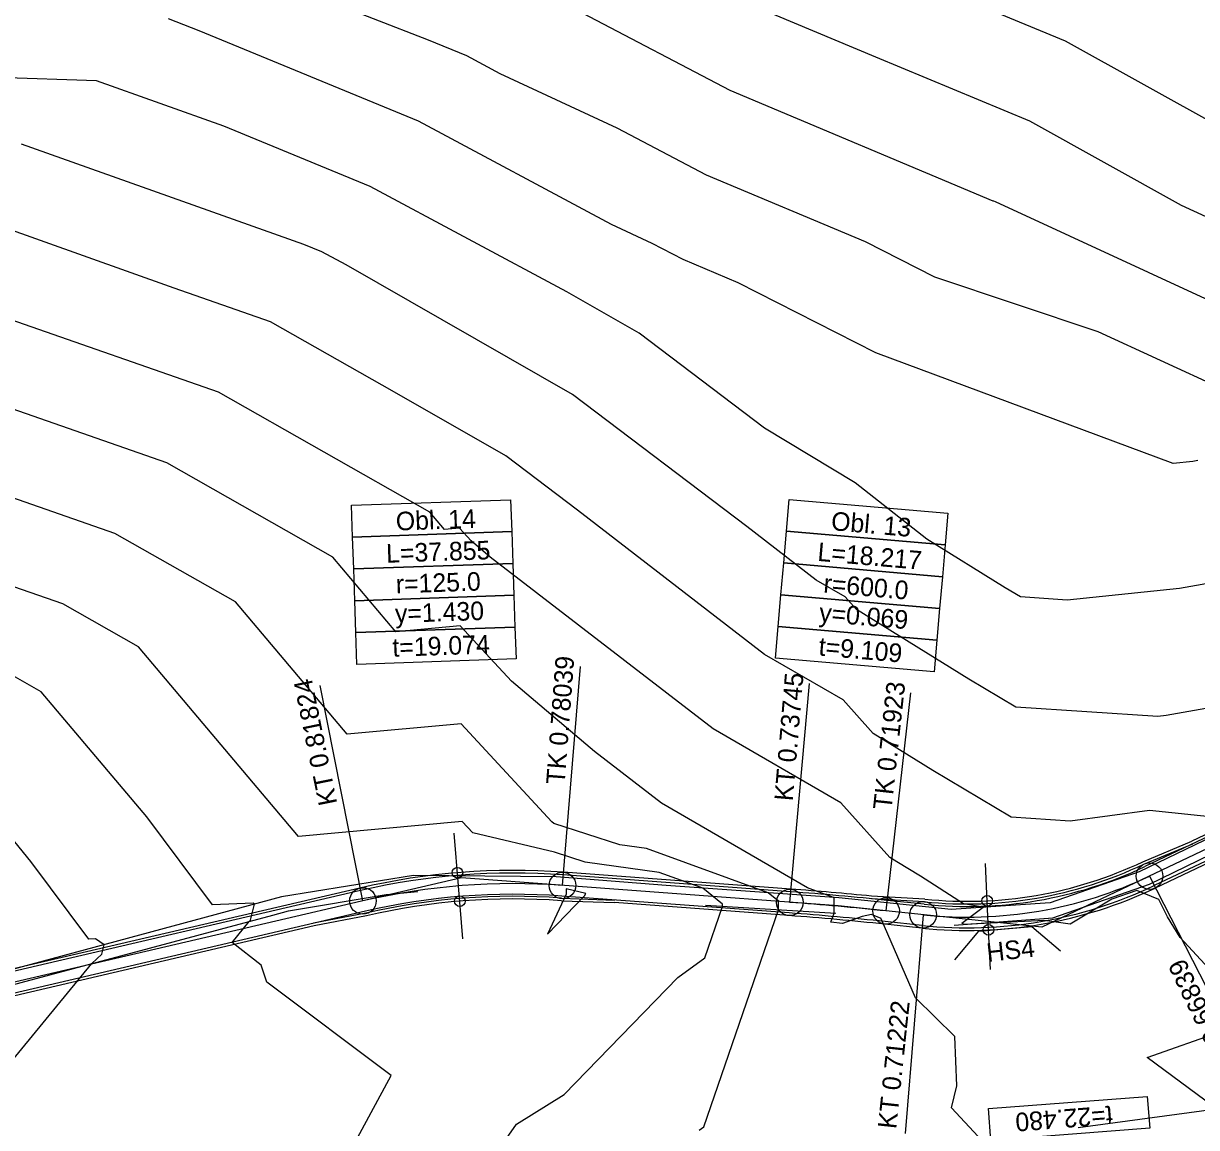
# Model space of a CAD drawing. Extents: x -549394 to -546608, y -1037055 to -1033629.
# Drawn here: x -548165.9 to -547944.9, y -1035508.1 to -1035300.1 of the extents above; entities that cross this region are included whole.
import ezdxf

# ---------------------------------------------------------------- set-up
doc = ezdxf.new("R2010")
doc.units = 0
for name, color, linetype in [('hlavni_vrst', 7, 'Continuous'), ('hrana_L', 7, 'Continuous'), ('norm_vrst', 7, 'Continuous'), ('POLYGONY_SITUACE_PO', 7, 'Continuous'), ('u_sirka_1_0m', 7, 'Continuous'), ('x_navrh_C1', 7, 'Continuous'), ('x_osa_C1', 7, 'Continuous'), ('x_popis_C1', 7, 'Continuous'), ('x_popis_oblouky_C1', 7, 'Continuous'), ('x_popis_pricne_rezy_C1', 7, 'Continuous')]:
    doc.layers.add(name, color=color, linetype=linetype)

msp = doc.modelspace()

# ---------------------------------------------------------------- linework, layer by layer
at = {"layer": 'hlavni_vrst'}
for p, q in [((-547969.61, -1035303.43), (-548019.52, -1035282.69)), ((-547912.21, -1035335.29), (-547969.61, -1035303.43)), ((-548152.18, -1035310.9), (-548239.54, -1035307.83)), ((-548128.21, -1035319.42), (-548152.18, -1035310.9)), ((-548100.61, -1035330.81), (-548128.21, -1035319.42)), ((-548063.57, -1035350.62), (-548100.61, -1035330.81)), ((-548049.94, -1035358.43), (-548063.57, -1035350.62)), ((-548026.31, -1035376.32), (-548049.94, -1035358.43)), ((-548148.73, -1035396.14), (-548210.36, -1035374.64)), ((-548009.25, -1035386.63), (-548026.31, -1035376.32)), ((-547995.73, -1035397.25), (-548009.25, -1035386.63)), ((-548125.97, -1035409.06), (-548148.73, -1035396.14)), ((-547980.98, -1035406.38), (-547995.73, -1035397.25)), ((-547933.91, -1035403.95), (-547948.12, -1035406.53)), ((-547978.09, -1035408.12), (-547980.98, -1035406.38)), ((-547969.28, -1035408.7), (-547978.09, -1035408.12)), ((-547948.12, -1035406.53), (-547969.28, -1035408.7)), ((-548104.95, -1035433.96), (-548125.97, -1035409.06)), ((-548083.44, -1035431.99), (-548104.95, -1035433.96)), ((-548066.37, -1035450.47), (-548083.44, -1035431.99)), ((-548066.01, -1035450.77), (-548066.37, -1035450.47)), ((-548053.6, -1035454.84), (-548066.01, -1035450.77)), ((-548048.53, -1035455.53), (-548053.6, -1035454.84)), ((-548025.63, -1035463.85), (-548048.53, -1035455.53)), ((-548023.69, -1035465.43), (-548025.63, -1035463.85)), ((-548023.71, -1035467.04), (-548023.69, -1035465.43)), ((-548037.74, -1035507.93), (-548023.71, -1035467.04)), ((-548038.63, -1035508.58), (-548037.74, -1035507.93))]:
    msp.add_line(p, q, dxfattribs=at)
at = {"layer": 'hrana_L'}
for p, q in [((-547937.9, -1035451.29), (-547955.7, -1035459.9)), ((-547953.79, -1035462.21), (-547936.33, -1035453.75)), ((-548092.43, -1035460.6), (-548117.3, -1035464.61)), ((-548065.59, -1035460.83), (-548092.43, -1035460.6)), ((-548044.85, -1035462.5), (-548065.59, -1035460.83)), ((-547955.7, -1035459.9), (-547972.5, -1035465.74)), ((-548097.61, -1035464.2), (-548091.63, -1035463.63)), ((-548012.33, -1035464.78), (-548044.85, -1035462.5)), ((-547972.01, -1035468.6), (-547953.79, -1035462.21)), ((-548117.3, -1035464.61), (-548191.5, -1035484.65)), ((-548115.99, -1035467.23), (-548097.61, -1035464.2)), ((-547991.14, -1035467), (-548012.33, -1035464.78)), ((-547972.5, -1035465.74), (-547991.14, -1035467)), ((-548189.89, -1035486.99), (-548118.94, -1035468.07)), ((-548118.94, -1035468.07), (-548115.99, -1035467.23)), ((-548037.46, -1035466.21), (-548012.89, -1035467.69)), ((-547990.56, -1035469.94), (-547972.01, -1035468.6))]:
    msp.add_line(p, q, dxfattribs=at)
at = {"layer": 'norm_vrst'}
for p, q in [((-548089.6, -1035303.24), (-548127.49, -1035288.48)), ((-548005.35, -1035306.45), (-548028.33, -1035296.81)), ((-548132.83, -1035301.46), (-548138.61, -1035299.21)), ((-548032.78, -1035312.73), (-548060.62, -1035298.12)), ((-548091.52, -1035318.5), (-548132.83, -1035301.46)), ((-548082.43, -1035306.19), (-548089.6, -1035303.24)), ((-548076.12, -1035309.57), (-548082.43, -1035306.19)), ((-547976.33, -1035318.51), (-548005.35, -1035306.45)), ((-548054.06, -1035319.81), (-548076.12, -1035309.57)), ((-547983.23, -1035333.52), (-548032.78, -1035312.73)), ((-548055.14, -1035337.96), (-548091.52, -1035318.5)), ((-548037.23, -1035328.65), (-548054.06, -1035319.81)), ((-547947.78, -1035334.36), (-547976.33, -1035318.51)), ((-548113.09, -1035341.72), (-548166.28, -1035322.8)), ((-548007.26, -1035341.22), (-548037.23, -1035328.65)), ((-548137.55, -1035349.93), (-548180.38, -1035334.7)), ((-547983.1, -1035333.58), (-547983.23, -1035333.52)), ((-547982.8, -1035333.68), (-547983.1, -1035333.58)), ((-547927.45, -1035359.27), (-547982.8, -1035333.68)), ((-547918.13, -1035348.07), (-547947.78, -1035334.36)), ((-548047.5, -1035341.5), (-548055.14, -1035337.96)), ((-548109.7, -1035343.12), (-548113.09, -1035341.72)), ((-548041.67, -1035344.56), (-548047.5, -1035341.5)), ((-547994.23, -1035347.86), (-548007.26, -1035341.22)), ((-548105.15, -1035345.55), (-548109.7, -1035343.12)), ((-548062.5, -1035369.98), (-548105.15, -1035345.55)), ((-548031.29, -1035348.92), (-548041.67, -1035344.56)), ((-547963.45, -1035358.14), (-547994.23, -1035347.86)), ((-548119.38, -1035356.27), (-548137.55, -1035349.93)), ((-548005.35, -1035362.14), (-548031.29, -1035348.92)), ((-548129.17, -1035369.56), (-548168.45, -1035355.86)), ((-548096.03, -1035369.52), (-548119.38, -1035356.27)), ((-547936.78, -1035370.47), (-547963.45, -1035358.14)), ((-548138.95, -1035382.85), (-548199.35, -1035361.78)), ((-548005.35, -1035362.14), (-548005.35, -1035362.14)), ((-547949.34, -1035382.95), (-548005.35, -1035362.14)), ((-548005.35, -1035362.14), (-548005.35, -1035362.14)), ((-548005.35, -1035362.14), (-548005.35, -1035362.14)), ((-548089.36, -1035392.15), (-548129.17, -1035369.56)), ((-548075.07, -1035381.53), (-548096.03, -1035369.52)), ((-548029.66, -1035394.85), (-548062.5, -1035369.98)), ((-548061.55, -1035391.77), (-548075.07, -1035381.53)), ((-548107.67, -1035400.6), (-548138.95, -1035382.85)), ((-547945.62, -1035382.57), (-547949.34, -1035382.95)), ((-547944.7, -1035382.4), (-547945.62, -1035382.57)), ((-548086.62, -1035395.39), (-548089.36, -1035392.15)), ((-548026.29, -1035418.94), (-548061.55, -1035391.77)), ((-548083.81, -1035395.14), (-548086.62, -1035395.39)), ((-548081.59, -1035397.55), (-548083.81, -1035395.14)), ((-548016.58, -1035404.93), (-548029.66, -1035394.85)), ((-548158.51, -1035409.43), (-548197.06, -1035395.99)), ((-548077.98, -1035400.6), (-548081.59, -1035397.55)), ((-548095.78, -1035414.68), (-548107.67, -1035400.6)), ((-548036, -1035432.95), (-548077.98, -1035400.6)), ((-548011.1, -1035408.12), (-548016.58, -1035404.93)), ((-548008.99, -1035410.46), (-548011.1, -1035408.12)), ((-548144.28, -1035417.51), (-548158.51, -1035409.43)), ((-547987.79, -1035423.59), (-548008.99, -1035410.46)), ((-548083.63, -1035413.56), (-548095.78, -1035414.68)), ((-548073.98, -1035424.01), (-548083.63, -1035413.56)), ((-548114.11, -1035453.24), (-548144.28, -1035417.51)), ((-548011.52, -1035427.52), (-548026.29, -1035418.94)), ((-548162.59, -1035425.97), (-548168.3, -1035422.73)), ((-547978.98, -1035428.86), (-547987.79, -1035423.59)), ((-548142.69, -1035449.53), (-548162.59, -1035425.97)), ((-548058.33, -1035437.23), (-548073.98, -1035424.01)), ((-547923.13, -1035425.49), (-547950.62, -1035430.48)), ((-548005.84, -1035433.84), (-548011.52, -1035427.52)), ((-547952.19, -1035430.64), (-547978.98, -1035428.86)), ((-547950.62, -1035430.48), (-547952.19, -1035430.64)), ((-548011.94, -1035446.93), (-548036, -1035432.95)), ((-547994.59, -1035440.8), (-548005.84, -1035433.84)), ((-548045.71, -1035446.96), (-548058.33, -1035437.23)), ((-548164.55, -1035457.95), (-548177.95, -1035441.52)), ((-547979.87, -1035449.61), (-547994.59, -1035440.8)), ((-548018.22, -1035462.93), (-548045.71, -1035446.96)), ((-548002.69, -1035457.21), (-548011.94, -1035446.93)), ((-548130.34, -1035466.12), (-548142.69, -1035449.53)), ((-548083.25, -1035450.41), (-548114.11, -1035453.24)), ((-548081.26, -1035452.57), (-548083.25, -1035450.41)), ((-547968.72, -1035450.35), (-547979.87, -1035449.61)), ((-547953.77, -1035448.32), (-547968.72, -1035450.35)), ((-547938.93, -1035449.9), (-547953.77, -1035448.32)), ((-548065.91, -1035456.19), (-548081.26, -1035452.57)), ((-548060.11, -1035458.09), (-548065.91, -1035456.19)), ((-548153.64, -1035472.6), (-548164.55, -1035457.95)), ((-548046.17, -1035460), (-548060.11, -1035458.09)), ((-548001.4, -1035458.01), (-548002.69, -1035457.21)), ((-547996.91, -1035460.69), (-548001.4, -1035458.01)), ((-548037.95, -1035462.98), (-548046.17, -1035460)), ((-547988.82, -1035465.93), (-547996.91, -1035460.69)), ((-548060, -1035464), (-548063.7, -1035463.12)), ((-548063.7, -1035463.12), (-548063.68, -1035464.11)), ((-548034.2, -1035466.02), (-548037.95, -1035462.98)), ((-548013.32, -1035464.71), (-548018.22, -1035462.93)), ((-547956.16, -1035463.44), (-547960.89, -1035465.04)), ((-547952, -1035465.1), (-547956.16, -1035463.44)), ((-548122.65, -1035465.82), (-548130.34, -1035466.12)), ((-548122.4, -1035465.99), (-548122.65, -1035465.82)), ((-548063.68, -1035464.11), (-548067.21, -1035471.66)), ((-548067.21, -1035471.66), (-548060.26, -1035464.43)), ((-548060.26, -1035464.43), (-548060, -1035464)), ((-548013.17, -1035464.83), (-548013.32, -1035464.71)), ((-548013.21, -1035467.67), (-548013.17, -1035464.83)), ((-547985.11, -1035466.59), (-547988.82, -1035465.93)), ((-547960.89, -1035465.04), (-547968.71, -1035469.77)), ((-547950.42, -1035468.35), (-547952, -1035465.1)), ((-548123.14, -1035469.03), (-548122.4, -1035465.99)), ((-548037.53, -1035476.08), (-548034.21, -1035466.41)), ((-548034.21, -1035466.41), (-548034.2, -1035466.02)), ((-548013.8, -1035469.41), (-548013.21, -1035467.67)), ((-548006.15, -1035467.95), (-548007.92, -1035468.32)), ((-548004.31, -1035468.7), (-548006.15, -1035467.95)), ((-547989.12, -1035469.6), (-547985.11, -1035466.59)), ((-548126.64, -1035473.22), (-548123.39, -1035469.26)), ((-548123.39, -1035469.26), (-548123.14, -1035469.03)), ((-548011.64, -1035469.61), (-548013.8, -1035469.41)), ((-548007.92, -1035468.32), (-548011.64, -1035469.61)), ((-548004.33, -1035468.76), (-548004.31, -1035468.7)), ((-547997.86, -1035483.64), (-548004.33, -1035468.76)), ((-547988.71, -1035469.81), (-547989.12, -1035469.6)), ((-547973.56, -1035469.05), (-547988.71, -1035469.81)), ((-547968.71, -1035469.77), (-547973.56, -1035469.05)), ((-547948.01, -1035472.3), (-547950.42, -1035468.35)), ((-548152.36, -1035472.55), (-548153.64, -1035472.6)), ((-548150.72, -1035473.64), (-548152.36, -1035472.55)), ((-547942.62, -1035478.12), (-547948.01, -1035472.3)), ((-548151.16, -1035475.43), (-548150.72, -1035473.64)), ((-548121.16, -1035477.49), (-548126.64, -1035473.22)), ((-548153.08, -1035477.17), (-548151.16, -1035475.43)), ((-548042.66, -1035479.8), (-548037.53, -1035476.08)), ((-548173.43, -1035501.96), (-548153.08, -1035477.17)), ((-548120.09, -1035480.68), (-548121.16, -1035477.49)), ((-548096.64, -1035498.3), (-548120.09, -1035480.68)), ((-548064.07, -1035501.86), (-548042.66, -1035479.8)), ((-547990.46, -1035490.94), (-547997.86, -1035483.64)), ((-547954.25, -1035494.86), (-547939.88, -1035489.82)), ((-547990.11, -1035500.23), (-547990.46, -1035490.94)), ((-547941.63, -1035504.16), (-547954.25, -1035494.86)), ((-548105.45, -1035514.49), (-548096.64, -1035498.3)), ((-547991.06, -1035504.34), (-547990.11, -1035500.23)), ((-548073.07, -1035507.45), (-548064.07, -1035501.86)), ((-547983.55, -1035512.45), (-547991.06, -1035504.34)), ((-547967.21, -1035508.09), (-547941.64, -1035504.6)), ((-548075.93, -1035511.56), (-548073.07, -1035507.45))]:
    msp.add_line(p, q, dxfattribs=at)
at = {"layer": 'POLYGONY_SITUACE_PO'}
for centre in [(-547953.77, -1035460.7), (-548064.37, -1035462.47), (-548101.97, -1035465.39), (-548021.55, -1035465.65), (-548003.41, -1035467.27), (-547996.43, -1035468)]:
    msp.add_circle(centre, 2.5, dxfattribs=at)
at = {"layer": 'u_sirka_1_0m'}
for centre in [(-548084.17, -1035460.07), (-548083.72, -1035465.43), (-547984.37, -1035465.36), (-547984.11, -1035470.84)]:
    msp.add_circle(centre, 1, dxfattribs=at)
at = {"layer": 'x_navrh_C1'}
for p, q in [((-547921.06, -1035442.95), (-547954.63, -1035458.89)), ((-547919.35, -1035446.56), (-547952.91, -1035462.5)), ((-547955.04, -1035457.99), (-547945.8, -1035454.14)), ((-547954.84, -1035458.45), (-547945.6, -1035454.6)), ((-548021.4, -1035463.65), (-548064.22, -1035460.48)), ((-548102.42, -1035463.44), (-548186.13, -1035482.93)), ((-548064.58, -1035465.35), (-548054.57, -1035465.71)), ((-548064.55, -1035464.85), (-548054.55, -1035465.21)), ((-548021.7, -1035467.64), (-548064.52, -1035464.47)), ((-547996.17, -1035465.53), (-548006.17, -1035464.98)), ((-547996.14, -1035465.03), (-548006.13, -1035464.48)), ((-547996.23, -1035466.01), (-548003.2, -1035465.28)), ((-548101.52, -1035467.34), (-548185.22, -1035486.83)), ((-548101.43, -1035467.71), (-548111.26, -1035469.6)), ((-548101.33, -1035468.2), (-548111.15, -1035470.09)), ((-547996.64, -1035469.99), (-548003.61, -1035469.26))]:
    msp.add_line(p, q, dxfattribs=at)
for points in [[(-547921.28, -1035442.5), (-547945.8, -1035454.14)], [(-547928.17, -1035451.31), (-547952.7, -1035462.96)], [(-548021.36, -1035463.16), (-548064.19, -1035459.98)], [(-548102.54, -1035462.95), (-548186.24, -1035482.45)], [(-548021.73, -1035468.14), (-548054.57, -1035465.71)], [(-548111.15, -1035470.09), (-548185.11, -1035487.32)], [(-547996.69, -1035470.49), (-548003.67, -1035469.76)], [(-547990.47, -1035476.48), (-547985.92, -1035471.08), (-547975.95, -1035470.23), (-547970.55, -1035474.79)]]:
    msp.add_lwpolyline(points, dxfattribs=at)
for centre, radius, start, end in [((-547988.1, -1035388.44), 78, 264.0191, 295.4098), ((-547988.1, -1035388.44), 77.51, 264.0191, 295.4098), ((-547988.1, -1035388.44), 77.01, 264.0099, 295.4189), ((-548073.62, -1035587.13), 127.5, 85.7587, 103.1102), ((-548073.62, -1035587.13), 127, 85.7587, 103.1102), ((-548065.92, -1036064.01), 602, 84.01915, 85.7587), ((-548065.92, -1036064.01), 602.5, 84.30485, 85.7587), ((-547988.1, -1035388.44), 82.5, 264.0191, 295.4098), ((-547988.1, -1035388.44), 82, 264.0191, 295.4098), ((-548073.62, -1035587.13), 123, 85.7587, 103.1102), ((-548073.62, -1035587.13), 122.62, 85.7587, 103.1102), ((-548073.62, -1035587.13), 122.12, 85.7542, 103.1147), ((-548065.92, -1036064.01), 597.5, 84.01915, 85.7587), ((-548065.92, -1036064.01), 598, 84.01915, 85.7587)]:
    msp.add_arc(centre, radius, start, end, dxfattribs=at)
at = {"layer": 'x_osa_C1'}
for points in [[(-547892.71, -1035431.69), (-547974.08, -1035470.34)], [(-548083.39, -1035461.06), (-548191.13, -1035486.15), (-548219.76, -1035492.15), (-548249.9, -1035495.61), (-548275.65, -1035501.47), (-548299.34, -1035504.6), (-548347.17, -1035498.12)], [(-547974.08, -1035470.34), (-548012.46, -1035466.32), (-548012.46, -1035466.32), (-548083.39, -1035461.06)]]:
    msp.add_lwpolyline(points, dxfattribs=at)
for centre, radius, start, end in [((-547988.1, -1035388.44), 80, 264.0191, 295.4098), ((-548073.62, -1035587.13), 125, 85.7587, 103.1102), ((-548065.92, -1036064.01), 600, 84.01915, 85.7587)]:
    msp.add_arc(centre, radius, start, end, dxfattribs=at)
at = {"layer": 'x_popis_oblouky_C1'}
for points in [[(-548104.13, -1035390.84), (-548074.15, -1035389.82), (-548073.95, -1035395.81), (-548103.93, -1035396.84)], [(-548021.65, -1035389.76), (-547991.77, -1035392.34), (-547992.28, -1035398.32), (-548022.17, -1035395.74)], [(-548103.93, -1035396.84), (-548073.95, -1035395.81), (-548073.74, -1035401.81), (-548103.72, -1035402.84)], [(-548022.17, -1035395.74), (-547992.28, -1035398.32), (-547992.8, -1035404.3), (-548022.69, -1035401.71)], [(-548103.72, -1035402.84), (-548073.74, -1035401.81), (-548073.54, -1035407.81), (-548103.52, -1035408.83)], [(-548022.69, -1035401.71), (-547992.8, -1035404.3), (-547993.32, -1035410.28), (-548023.21, -1035407.69)], [(-548103.52, -1035408.83), (-548073.54, -1035407.81), (-548073.33, -1035413.8), (-548103.31, -1035414.83)], [(-548023.21, -1035407.69), (-547993.32, -1035410.28), (-547993.83, -1035416.25), (-548023.72, -1035413.67)], [(-548103.31, -1035414.83), (-548073.33, -1035413.8), (-548073.13, -1035419.8), (-548103.11, -1035420.83)], [(-548023.72, -1035413.67), (-547993.83, -1035416.25), (-547994.35, -1035422.23), (-548024.24, -1035419.65)], [(-547953.74, -1035508.2), (-547983.65, -1035510.5), (-547984.11, -1035504.52), (-547954.2, -1035502.21)]]:
    msp.add_lwpolyline(points, close=True, dxfattribs=at)
for points in [[(-548064.37, -1035462.47), (-548061.01, -1035421.24)], [(-548101.97, -1035465.39), (-548110.04, -1035424.81)], [(-548021.55, -1035465.65), (-548017.84, -1035424.44)], [(-548003.41, -1035467.27), (-547998.72, -1035426.16)], [(-547953.77, -1035460.7), (-547934.91, -1035497.52)], [(-547996.43, -1035468), (-547999.84, -1035509.23)]]:
    msp.add_lwpolyline(points, dxfattribs=at)
at = {"layer": 'x_popis_pricne_rezy_C1'}
for points in [[(-548083.14, -1035472.52), (-548083.96, -1035462.56), (-548084.79, -1035452.59)], [(-547983.75, -1035478.33), (-547984.23, -1035468.34), (-547984.71, -1035458.36)]]:
    msp.add_lwpolyline(points, dxfattribs=at)

# ---------------------------------------------------------------- texts
at = {"layer": 'x_popis_C1'}
msp.add_text('HS4', height=3.5, rotation=6.4323, dxfattribs=at).set_placement((-547984.28, -1035476.88))
at = {"layer": 'x_popis_oblouky_C1'}
for s, rotation, p in [('Obl. 14', 1.9784, (-548095.72, -1035395.61)), ('Obl. 13', 355.08, (-548013.87, -1035395.51)), ('L=37.855', 1.9784, (-548097.55, -1035401.68)), ('L=18.217', 355.08, (-548016.42, -1035401.31)), ('r=125.0', 1.9784, (-548095.72, -1035407.45)), ('r=600.0', 355.08, (-548015.3, -1035407.26)), ('y=1.430', 1.9784, (-548095.88, -1035413.02)), ('y=0.069', 355.08, (-548016.13, -1035412.76)), ('t=19.074', 1.9784, (-548096.36, -1035419.39)), ('t=9.109', 355.08, (-548016.21, -1035419.13)), ('TK 0.78039', 85.6448, (-548063.98, -1035443.51)), ('KT 0.81824', 101.5518, (-548106.8, -1035447.01)), ('KT 0.73745', 85.1581, (-548020.99, -1035446.66)), ('TK 0.71923', 83.7982, (-548002.4, -1035448.33)), ('TK 0.66839', 115.7496, (-547936.73, -1035497.77)), ('KT 0.71222', 83.9063, (-548001.51, -1035508.44)), ('t=22.480', 184.4206, (-547960.88, -1035503.94))]:
    msp.add_text(s, height=3.5, rotation=rotation, dxfattribs=at).set_placement(p)

doc.saveas('drawing.dxf')
